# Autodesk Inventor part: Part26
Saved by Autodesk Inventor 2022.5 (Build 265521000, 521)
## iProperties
Created: 2024-07
Part Number: Part26
Material: Generic
Document SubType Name: Modeling
Designer: AdminForWorker
Density: 1 g/cm^3
Appearance: Default
Author: AdminForWorker
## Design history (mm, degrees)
feature "BU-T10-5-LED-120V"
body "Solid1"
